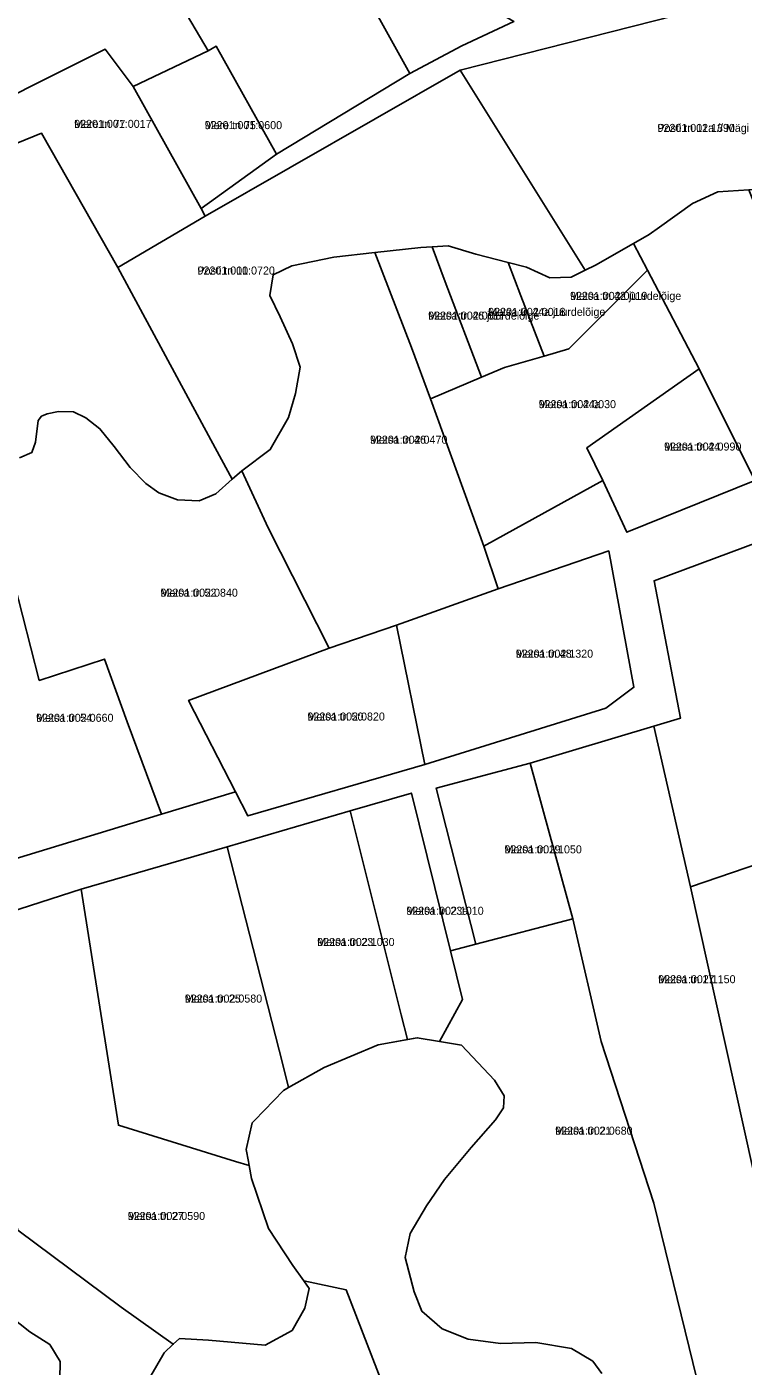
# Model space of a CAD drawing. Extents: x 601493 to 643081, y 6584980 to 6634019.
# Drawn here: x 610619.4 to 610753.7, y 6605570.9 to 6605821.9 of the extents above; entities that cross this region are included whole.
import ezdxf

# ---------------------------------------------------------------- set-up
doc = ezdxf.new("R2010")
doc.units = 0
for name, color, linetype in [('L_AADRESS', 7, 'Continuous'), ('PIIR', 7, 'Continuous'), ('TUNNUS', 7, 'Continuous')]:
    doc.layers.add(name, color=color, linetype=linetype)

msp = doc.modelspace()

# ---------------------------------------------------------------- linework, layer by layer
at = {"layer": 'PIIR'}
for points in [[(610691.22, 6605813.21), (610664.76, 6605860.79), (610682.23, 6605871.18), (610698.96, 6605840.26), (610700.04, 6605840.62), (610708.76, 6605824.04), (610710.71, 6605822.92), (610700.95, 6605818.39)], [(610653.37, 6605817.46), (610636.89, 6605845.42), (610664.76, 6605860.79), (610691.22, 6605813.21), (610666.19, 6605798.08), (610654.87, 6605818.34)], [(610593.01, 6605821.27), (610636.89, 6605845.42), (610653.37, 6605817.46), (610639.31, 6605810.75), (610634.12, 6605817.74), (610603.72, 6605802.55)], [(610724.08, 6605776.33), (610716.89, 6605787.82), (610700.61, 6605813.84), (610757, 6605828.16), (610770.02, 6605795.62), (610772.28, 6605789.54), (610771.22, 6605789.5), (610763.94, 6605790.43), (610756.17, 6605791.47), (610754.72, 6605791.37), (610748.92, 6605790.98), (610744.19, 6605788.8), (610738.01, 6605784.38), (610736.06, 6605782.98), (610733.11, 6605781.31), (610725.97, 6605777.27)], [(610639.31, 6605810.75), (610653.37, 6605817.46), (610654.87, 6605818.34), (610666.19, 6605798.08), (610652.09, 6605787.88)], [(610634.12, 6605817.74), (610639.31, 6605810.75), (610652.09, 6605787.88), (610652.85, 6605786.44), (610636.44, 6605776.8), (610622.16, 6605801.98), (610607.42, 6605796.01), (610603.72, 6605802.55)], [(610676.98, 6605778.74), (610669.09, 6605777.16), (610665.58, 6605775.47), (610664.97, 6605771.58), (610666.91, 6605767.58), (610669.21, 6605762.49), (610670.67, 6605758.12), (610669.78, 6605753.22), (610668.43, 6605748.68), (610665.03, 6605742.7), (610659.7, 6605738.72), (610657.87, 6605737.17), (610653.89, 6605744.53), (610636.44, 6605776.8), (610652.85, 6605786.44), (610700.61, 6605813.84), (610716.89, 6605787.82), (610724.08, 6605776.33), (610721.43, 6605775), (610717.41, 6605774.9), (610713.08, 6605776.86), (610709.6, 6605777.77), (610703.56, 6605779.34), (610698.41, 6605780.89), (610695.4, 6605780.71), (610693.25, 6605780.58), (610684.62, 6605779.61)], [(610755.86, 6605736.89), (610745.42, 6605757.82), (610735.74, 6605776.32), (610733.11, 6605781.31), (610736.06, 6605782.98), (610738.01, 6605784.38), (610744.19, 6605788.8), (610748.92, 6605790.98), (610754.72, 6605791.37), (610760.65, 6605776.64), (610774.92, 6605741.12)], [(610697.83, 6605774.13), (610704.64, 6605756.25), (610695.09, 6605752.22), (610691.5, 6605761.85), (610684.62, 6605779.61), (610693.25, 6605780.58), (610695.4, 6605780.71)], [(610711.98, 6605771.52), (610716.35, 6605760.22), (610708.94, 6605758.07), (610704.64, 6605756.25), (610697.83, 6605774.13), (610695.4, 6605780.71), (610698.41, 6605780.89), (610703.56, 6605779.34), (610709.6, 6605777.77)], [(610724.08, 6605776.33), (610725.97, 6605777.27), (610733.11, 6605781.31), (610735.74, 6605776.32), (610720.97, 6605761.58), (610716.35, 6605760.22), (610711.98, 6605771.52), (610709.6, 6605777.77), (610713.08, 6605776.86), (610717.41, 6605774.9), (610721.43, 6605775)], [(610664.66, 6605728.04), (610659.7, 6605738.72), (610665.03, 6605742.7), (610668.43, 6605748.68), (610669.78, 6605753.22), (610670.67, 6605758.12), (610669.21, 6605762.49), (610666.91, 6605767.58), (610664.97, 6605771.58), (610665.58, 6605775.47), (610669.09, 6605777.16), (610676.98, 6605778.74), (610684.62, 6605779.61), (610691.5, 6605761.85), (610695.09, 6605752.22), (610705.04, 6605724.61), (610707.75, 6605716.62), (610688.67, 6605709.81), (610676.05, 6605705.45)], [(610745.42, 6605757.82), (610724.37, 6605743.01), (610727.39, 6605736.88), (610705.04, 6605724.61), (610695.09, 6605752.22), (610704.64, 6605756.25), (610708.94, 6605758.07), (610716.35, 6605760.22), (610720.97, 6605761.58), (610735.74, 6605776.32)], [(610727.39, 6605736.88), (610724.37, 6605743.01), (610745.42, 6605757.82), (610755.86, 6605736.89), (610731.89, 6605727.19)], [(610736.92, 6605690.82), (610741.9, 6605692.35), (610736.99, 6605718.1), (610762.69, 6605727.65), (610782.16, 6605673.79), (610779.86, 6605673.07), (610743.83, 6605660.73)], [(610688.67, 6605709.81), (610707.75, 6605716.62), (610728.47, 6605723.7), (610733.21, 6605698.14), (610727.92, 6605694.21), (610694.04, 6605683.68)], [(610608.77, 6605681.37), (610602.57, 6605695.06), (610603.27, 6605698.07), (610610.74, 6605709.16), (610617.06, 6605717.8), (610621.73, 6605699.44), (610633.98, 6605703.42), (610638.2, 6605691.66), (610644.68, 6605674.38), (610615.77, 6605665.54)], [(610658.54, 6605678.56), (610649.73, 6605695.69), (610676.05, 6605705.45), (610688.67, 6605709.81), (610694.04, 6605683.68), (610660.83, 6605674.02)], [(610736.95, 6605601.41), (610727.06, 6605631.76), (610721.77, 6605654.74), (610713.75, 6605683.91), (610736.92, 6605690.82), (610743.83, 6605660.73), (610758.89, 6605592.68), (610761.75, 6605580.09), (610761.33, 6605574.93), (610759.58, 6605570.71), (610756.17, 6605567.2), (610746.6, 6605561.79), (610745, 6605568.53)], [(610696.11, 6605679.21), (610713.75, 6605683.91), (610721.77, 6605654.74), (610703.58, 6605649.99)], [(610680.02, 6605674.96), (610691.49, 6605678.3), (610698.8, 6605648.75), (610701.05, 6605639.64), (610696.79, 6605631.74), (610692.58, 6605632.45), (610690.75, 6605632.12), (610689.58, 6605636.77)], [(610667.39, 6605627.44), (610656.94, 6605668.21), (610680.02, 6605674.96), (610689.58, 6605636.77), (610690.75, 6605632.12), (610685.26, 6605631.11), (610675.15, 6605626.88), (610668.46, 6605623.09)], [(610743.83, 6605660.73), (610779.86, 6605673.07), (610781.67, 6605665.57), (610789.07, 6605634.6), (610791.88, 6605622.82), (610789.57, 6605623.17), (610786.44, 6605623.82), (610782.81, 6605623.91), (610778.86, 6605623.49), (610776.31, 6605622.06), (610773.28, 6605620), (610769.64, 6605616.96), (610766.36, 6605612.48), (610765.03, 6605609.57), (610764.18, 6605605.32), (610762.84, 6605598.77), (610762.72, 6605591), (610762.35, 6605585.3), (610761.75, 6605580.09), (610758.89, 6605592.68)], [(610629.58, 6605660.29), (610656.94, 6605668.21), (610667.39, 6605627.44), (610668.46, 6605623.09), (610667.52, 6605622.56), (610662.08, 6605616.93), (610661.64, 6605616.47), (610660.51, 6605611.53), (610660.93, 6605609.25), (610661.08, 6605608.5), (610658.53, 6605609.22), (610636.59, 6605616.03)], [(610617.75, 6605596.36), (610604.29, 6605649.91), (610606.64, 6605652.9), (610629.58, 6605660.29), (610636.59, 6605616.03), (610658.53, 6605609.22), (610661.08, 6605608.5), (610661.53, 6605606.06), (610664.72, 6605596.68), (610669.26, 6605589.77), (610671.34, 6605586.86), (610672.35, 6605585.44), (610671.52, 6605581.73), (610669.15, 6605577.6), (610664.09, 6605574.82), (610653.47, 6605575.75), (610648.01, 6605576.06), (610646.85, 6605574.99), (610637.1, 6605581.95)]]:
    msp.add_lwpolyline(points, close=True, dxfattribs=at)
for points in [[(610757, 6605828.16), (610700.61, 6605813.84), (610652.85, 6605786.44), (610652.09, 6605787.88), (610666.19, 6605798.08), (610691.22, 6605813.21), (610700.95, 6605818.39), (610710.71, 6605822.92)], [(610607.42, 6605796.01), (610622.16, 6605801.98), (610636.44, 6605776.8), (610653.89, 6605744.53), (610657.87, 6605737.17), (610654.81, 6605734.39), (610651.71, 6605733.07), (610647.67, 6605733.26), (610644.16, 6605734.59), (610641.69, 6605736.32), (610638.8, 6605739.31), (610635.8, 6605743.25), (610633.1, 6605746.59), (610630.49, 6605748.62), (610628.15, 6605749.74), (610625.33, 6605749.81), (610623.21, 6605749.37), (610622.17, 6605748.94), (610621.51, 6605748.13), (610621.02, 6605744.07), (610620.36, 6605742.15), (610618.06, 6605741.14)], [(610618.06, 6605741.14), (610620.36, 6605742.15), (610621.02, 6605744.07), (610621.51, 6605748.13), (610622.17, 6605748.94), (610623.21, 6605749.37), (610625.33, 6605749.81), (610628.15, 6605749.74), (610630.49, 6605748.62), (610633.1, 6605746.59), (610635.8, 6605743.25), (610638.8, 6605739.31), (610641.69, 6605736.32), (610644.16, 6605734.59), (610647.67, 6605733.26), (610651.71, 6605733.07), (610654.81, 6605734.39), (610657.87, 6605737.17), (610659.7, 6605738.72), (610664.66, 6605728.04), (610676.05, 6605705.45), (610649.73, 6605695.69), (610658.54, 6605678.56), (610644.68, 6605674.38), (610638.2, 6605691.66), (610633.98, 6605703.42), (610621.73, 6605699.44), (610617.06, 6605717.8)], [(610615.77, 6605665.54), (610644.68, 6605674.38), (610658.54, 6605678.56), (610660.83, 6605674.02), (610694.04, 6605683.68), (610727.92, 6605694.21), (610733.21, 6605698.14), (610728.47, 6605723.7), (610707.75, 6605716.62), (610705.04, 6605724.61), (610727.39, 6605736.88), (610731.89, 6605727.19), (610755.86, 6605736.89)], [(610762.69, 6605727.65), (610736.99, 6605718.1), (610741.9, 6605692.35), (610736.92, 6605690.82), (610713.75, 6605683.91), (610696.11, 6605679.21), (610703.58, 6605649.99), (610698.8, 6605648.75), (610691.49, 6605678.3), (610680.02, 6605674.96), (610656.94, 6605668.21), (610629.58, 6605660.29), (610606.64, 6605652.9), (610604.29, 6605649.91), (610617.75, 6605596.36), (610637.1, 6605581.95), (610646.85, 6605574.99), (610645.12, 6605573.38), (610644.87, 6605572.95), (610641.1, 6605566.37)], [(610727.17, 6605569.54), (610725.52, 6605571.8), (610721.5, 6605574.18), (610714.8, 6605575.31), (610708.2, 6605575.11), (610702.12, 6605575.93), (610697.28, 6605577.89), (610693.46, 6605581.19), (610691.99, 6605584.83), (610690.3, 6605591.26), (610691.27, 6605595.74), (610694.3, 6605600.96), (610697.69, 6605605.88), (610702.67, 6605611.88), (610707.28, 6605617.09), (610708.74, 6605619.28), (610708.86, 6605621.58), (610707.04, 6605624.49), (610700.86, 6605631.04), (610696.79, 6605631.74), (610701.05, 6605639.64), (610698.8, 6605648.75), (610703.58, 6605649.99), (610721.77, 6605654.74), (610727.06, 6605631.76), (610736.95, 6605601.41), (610745, 6605568.53)], [(610708.65, 6605509.22), (610679.24, 6605585.22), (610671.34, 6605586.86), (610669.26, 6605589.77), (610664.72, 6605596.68), (610661.53, 6605606.06), (610661.08, 6605608.5), (610660.93, 6605609.25), (610660.51, 6605611.53), (610661.64, 6605616.47), (610662.08, 6605616.93), (610667.52, 6605622.56), (610668.46, 6605623.09), (610675.15, 6605626.88), (610685.26, 6605631.11), (610692.58, 6605632.45), (610696.79, 6605631.74), (610700.86, 6605631.04), (610707.04, 6605624.49), (610708.86, 6605621.58), (610708.74, 6605619.28), (610707.28, 6605617.09), (610702.67, 6605611.88), (610697.69, 6605605.88), (610694.3, 6605600.96), (610691.27, 6605595.74), (610690.3, 6605591.26), (610691.99, 6605584.83), (610693.46, 6605581.19), (610697.28, 6605577.89), (610702.12, 6605575.93), (610708.2, 6605575.11), (610714.8, 6605575.31), (610721.5, 6605574.18), (610725.52, 6605571.8), (610727.17, 6605569.54)], [(610593.98, 6605566.48), (610595.22, 6605573.18), (610596.98, 6605578.54), (610601.62, 6605584.11), (610604.65, 6605585.68), (610610.01, 6605583.94), (610614.85, 6605581.36), (610620, 6605577.34), (610623.71, 6605574.97), (610625.67, 6605571.77), (610625.57, 6605568.47)], [(610641.1, 6605566.37), (610644.87, 6605572.95), (610645.12, 6605573.38), (610646.85, 6605574.99), (610648.01, 6605576.06), (610653.47, 6605575.75), (610664.09, 6605574.82), (610669.15, 6605577.6), (610671.52, 6605581.73), (610672.35, 6605585.44), (610671.34, 6605586.86), (610679.24, 6605585.22), (610708.65, 6605509.22)], [(610625.57, 6605568.47), (610625.67, 6605571.77), (610623.71, 6605574.97), (610620, 6605577.34), (610614.85, 6605581.36)]]:
    msp.add_lwpolyline(points, dxfattribs=at)

# ---------------------------------------------------------------- texts
at = {"layer": 'L_AADRESS'}
for s, p in [('Mere tn 77', (610628.29, 6605803)), ('Mere tn 75', (610652.75, 6605802.76)), ('Posti tn 12a // Mägi', (610737.62, 6605802.24)), ('Posti tn 10', (610651.4, 6605775.51)), ('Metsa tn 42 juurdelõige', (610721.22, 6605770.76)), ('Metsa tn 46 juurdelõige', (610694.63, 6605767.06)), ('Metsa tn 44a juurdelõige', (610705.88, 6605767.76)), ('Metsa tn 44a', (610715.34, 6605750.46)), ('Metsa tn 46', (610683.73, 6605743.8)), ('Metsa tn 44', (610738.84, 6605742.51)), ('Metsa tn 52', (610644.46, 6605715.12)), ('Metsa tn 48', (610711.05, 6605703.69)), ('Metsa tn 54', (610621.15, 6605691.67)), ('Metsa tn 50', (610672.01, 6605691.91)), ('Metsa tn 19', (610708.94, 6605667.01)), ('Metsa tn 23a', (610690.54, 6605655.5)), ('Metsa tn 23', (610673.84, 6605649.65)), ('Metsa tn 17', (610737.75, 6605642.67)), ('Metsa tn 25', (610649.02, 6605639.04)), ('Metsa tn 21', (610718.45, 6605614.28)), ('Metsa tn 27', (610638.32, 6605598.29))]:
    msp.add_text(s, height=1.5, dxfattribs=at).set_placement(p)
at = {"layer": 'TUNNUS'}
for s, p in [('92201:001:0017', (610628.29, 6605803)), ('92201:001:0600', (610652.75, 6605802.76)), ('92201:001:1390', (610737.62, 6605802.24)), ('92201:001:0720', (610651.4, 6605775.51)), ('92201:002:0019', (610721.22, 6605770.76)), ('92201:002:0017', (610694.63, 6605767.06)), ('92201:002:0018', (610705.88, 6605767.76)), ('92201:002:0030', (610715.34, 6605750.46)), ('92201:002:0470', (610683.73, 6605743.8)), ('92201:002:0990', (610738.84, 6605742.51)), ('92201:002:0840', (610644.46, 6605715.12)), ('92201:002:1320', (610711.05, 6605703.69)), ('92201:002:0660', (610621.15, 6605691.67)), ('92201:002:0820', (610672.01, 6605691.91)), ('92201:002:1050', (610708.94, 6605667.01)), ('92201:002:1010', (610690.54, 6605655.5)), ('92201:002:1030', (610673.84, 6605649.65)), ('92201:002:1150', (610737.75, 6605642.67)), ('92201:002:0580', (610649.02, 6605639.04)), ('92201:002:0680', (610718.45, 6605614.28)), ('92201:002:0590', (610638.32, 6605598.29))]:
    msp.add_text(s, height=1.5, dxfattribs=at).set_placement(p)

doc.saveas('drawing.dxf')
